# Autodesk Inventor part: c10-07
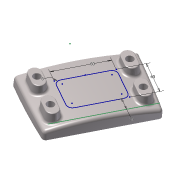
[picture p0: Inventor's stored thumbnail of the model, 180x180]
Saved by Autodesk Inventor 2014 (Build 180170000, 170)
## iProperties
Created: 2010-12
Part Number: c10-07
Material: Generic
Document SubType Name: Modeling
Designer: Thom Tremblay
Density: 1 g/cm^3
Appearance: Generic
Author: Thom Tremblay
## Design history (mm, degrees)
sketch "Sketch1"
  geometry: L1 (-60, -12)-(60, -12); L2 (60, -12)-(60, 12); L3 (60, 12)-(-60, 12); L4 (-60, 12)-(-60, -12); A1 r 350 centre (0, -332.819) between (60, 12) and (-60, 12); A2 r 350 centre (0, 332.819) between (-60, -12) and (60, -12); 3 further points
  constraints: 8 end point, 4 point on circle, 2 centre point, 2 midpoint, 2 parallel, 1 equal radius, 1 horizontal, 1 horizontal alignment, 1 perpendicular, 1 vertical alignment
  dimensions: "d0" = 120 distance of L3.end L2.end; "d1" = 24 distance of L2.end L1.end; "d2" = 350 radius of A1
workplane "Work Plane4"
sketch "Sketch5"
  geometry: L1 (-60, 12)-(-60, -12) reference; L2 (60, -12)-(60, 12) reference; L3 (-58, 10.314)-(-58, -10.314); L4 (58, -10.314)-(58, 10.314); A1 r 350 centre (0, 332.819) between (-60, -12) and (60, -12) reference; A2 r 350 centre (0, -332.819) between (60, 12) and (-60, 12) reference; A3 r 348 centre (0, 332.819) between (-58, -10.314) and (58, -10.314); A4 r 348 centre (0, -332.819) between (58, 10.314) and (-58, 10.314); 1 further point
  constraints: 4 end point, 4 point on circle, 2 centre point, 3 other
  dimensions: "d37" = 2 distance between parallel lines of L2 L4
sketch "Sketch6"
  geometry: L1 (-60, 0)-(60, 0); L2 (60, 0)-(58.843, 22.085); L3 (-60, 0)-(-58.779, 23.307); A1 r 691.758 centre (630.81, -36.204) between (-60, 0) and (-58, -100); A2 r 691.758 centre (-630.81, -36.204) between (58, -100) and (60, 0); 1 further point
  constraints: 6 end point, 4 point on circle, 2 centre point, 2 tangent, 1 horizontal
  dimensions: "d53" = 87 deg angle of L1 L3; "d54" = 87 deg angle of L1 L2 (= d53)
sketch "Sketch7"
  geometry: L1 (17.181, 0)-(12, 0) reference; L2 (15.181, -100)-(10.314, -100) reference; L3 (17.181, 0)-(16.768, 11.838); A1 r 911.322 centre (-893.585, -31.805) between (15.181, -100) and (17.181, 0); 1 further point
  constraints: 2 end point, 2 point on circle, 1 centre point, 1 tangent
  dimensions: "d56" = 88 deg angle of L1 L3
feature "LoftSrf2" sketch "Sketch5", "Sketch6", "Sketch7" dims "d57" = 0, "d58" = 90 deg, "d59" = 0, "d60" = 90 deg, "d61" = 0, "d62" = 90 deg, "d63" = 0, "d64" = 90 deg, "d65" = 0, "d66" = 90 deg
sketch "Sketch2"
  geometry: L1 (-75, -16)-(75, -16); L2 (-75, -60)-(75, -60); A1 r 183.781 centre (0, -183.781) between (75, -16) and (-75, -16); 2 further points
  constraints: 4 end point, 3 point on circle, 1 centre point, 1 coincident, 1 horizontal, 1 parallel
  dimensions: "d5" = 16 distance from line of point (0, 0) L1; "d7" = 60 distance from line of point (0, 0) L2; "d55" = 150 distance of L1.start L1.end
feature "RevolutionSrf1" sketch "Sketch2" dims angle "d8" = 40 deg
patch "Boundary Patch1" dims "d13" = 0, "d67" = 0, "d68" = 0, "d69" = 0, "d70" = 0
workplane "Work Plane1"
sketch "Sketch3"
  geometry: L1 (52, -85)-(52, -73); L2 (38, -73)-(38, -85); A1 r 7 centre (45, -73) between (52, -73) and (38, -73); A2 r 7 centre (45, -85) between (38, -85) and (52, -85); 1 further point
  constraints: 4 end point, 4 point on circle, 4 tangent, 2 centre point, 1 parallel, 1 vertical
  dimensions: "d15" = 12 distance of L1.start L1.end; "d16" = 7 radius of A1; "d50" = 45 horizontal distance of A1.centre point (0, 0); "d51" = 85 vertical distance of point (0, 0) A2.centre
extrude_surface "ExtrusionSrf2" sketch "Sketch3" dims "d19" = 14, "d20" = 5 deg
pattern_linear "Rectangular Pattern1" dims "d23" = 90
workplane "Work Plane2"
feature "Sculpt1"
sketch "Sketch4"
  geometry: L1 (-24.5, 6)-(24.5, 6); L2 (27.5, 3)-(27.5, -3); L3 (24.5, -6)-(-24.5, -6); L4 (-27.5, -3)-(-27.5, 3); A1 r 3 centre (-24.5, 3) between (-24.5, 6) and (-27.5, 3); A2 r 3 centre (24.5, 3) between (27.5, 3) and (24.5, 6); A3 r 3 centre (24.5, -3) between (24.5, -6) and (27.5, -3); A4 r 3 centre (-24.5, -3) between (-27.5, -3) and (-24.5, -6); 6 further points
  constraints: 8 end point, 8 point on circle, 8 tangent, 6 point on line, 4 centre point, 3 equal radius, 2 midpoint, 2 parallel, 1 horizontal, 1 horizontal alignment, 1 perpendicular, 1 vertical alignment
  dimensions: "d28" = 55 distance of point (27.5, -6) point (-27.5, -6); "d29" = 12 distance of point (27.5, 6) point (27.5, -6); "d30" = 3 radius of A1
extrude_surface "ExtrusionSrf6" sketch "Sketch4" dims "d31" = 14, "d32" = 45 deg
patch "Boundary Patch2" dims "d33" = 0, "d34" = 0
fillet "Fillet1" dims "d79" = 4, "d80" = 3, "d81" = 1
feature "Sculpt2"
node "Splitting Plane 1"
shell "Shell1" dims "d83" = 2
split "Split1"
  body "Solid1"
feature "Lip1" dims "d142" = 1, "d143" = 1, "d144" = 0, "d145" = 0, "d146" = 0, "d147" = 0
feature "Lip2" dims "d148" = 1, "d149" = 1, "d150" = 0, "d151" = 0, "d152" = 0, "d153" = 0.5
split "Split3"
  node "Back"
sketch "Sketch9"
  geometry: L1 (50.167, -73)-(50.167, -85) reference; L2 (39.833, -85)-(39.833, -73) reference; L3 (45, -73)-(45, -85); L4 (45, -85)-(39.833, -85); A1 r 5.167 centre (45, -73) between (50.167, -73) and (39.833, -73) reference; A2 r 5.167 centre (45, -85) between (39.833, -85) and (50.167, -85) reference; 5 further points
  constraints: 4 end point, 1 horizontal, 1 midpoint, 1 parallel, 1 perpendicular, 1 vertical, 3 other
  dimensions: "d86" = 90 distance of point (45, -79) point (-45, -79); "d89" = 40 distance of point (45, -79) point (45, -39)
  node "Projected Loop1"
feature "Boss1" dims "d92" = 0, "d93" = 0, "d94" = 7, "d95" = 2, "d96" = 0.5, "d97" = 6, "d98" = 1.25, "d99" = 3.5, "d100" = 2.5 deg, "d101" = 2.5 deg, "d102" = 2.5 deg, "d103" = 2.5 deg, "d104" = 90 deg, "d107" = 2, "d108" = 2, "d109" = 10, "d110" = 0, "d111" = 10 deg, "d112" = 2.5 deg, "d113" = 0, "d114" = 0, "d115" = 0, "d116" = 360 deg
feature "Boss2" dims "d117" = 3, "d118" = 0, "d119" = 6, "d120" = 3, "d121" = 9.5, "d122" = 2 deg, "d123" = 1 deg, "d126" = 2, "d127" = 2, "d128" = 10, "d129" = 0, "d130" = 10 deg, "d131" = 2.5 deg, "d132" = 0, "d133" = 0, "d134" = 0, "d135" = 360 deg
workplane "Work Plane6"
sketch "Sketch10"
  geometry: L1 (24, -85)-(-24, -85); L2 (-30, -79)-(-30, -51); L3 (-24, -45)-(24, -45); L4 (30, -51)-(30, -79); L5 (54.344, -100)-(-54.344, -100) reference; A1 r 6 centre (-24, -51) between (-24, -45) and (-30, -51); A2 r 6 centre (24, -51) between (30, -51) and (24, -45); A3 r 6 centre (24, -79) between (24, -85) and (30, -79); A4 r 6 centre (-24, -79) between (-30, -79) and (-24, -85); 5 further points
  constraints: 8 end point, 8 point on circle, 8 tangent, 6 point on line, 4 centre point, 3 equal radius, 2 parallel, 1 horizontal, 1 midpoint, 1 perpendicular, 1 vertical alignment
  dimensions: "d137" = 60 distance of point (-30, -45) point (30, -45); "d138" = 40 distance of point (-30, -85) point (-30, -45); "d139" = 15 distance between parallel lines of L5 L1; "d141" = 6 radius of A2
body "Srf2"
body "Srf3"
body "Srf4"
body "Srf5"
body "Srf6"
body "Srf7"
body "Srf8"
body "Srf9"
body "Srf11"
feature "Stitch Surface1"
body "Srf12"
extrude_surface "ExtrusionSrf3"
extrude_surface "ExtrusionSrf4"
extrude_surface "ExtrusionSrf5"
node "Front"
node "Back - Top"
node "Back - Bottom"
other parameters: "d14" = -24, "d52" = -6
